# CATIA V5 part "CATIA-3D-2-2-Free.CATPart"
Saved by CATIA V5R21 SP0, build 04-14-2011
Part number: CATIA-3D-2-2-Free
Bounding box of the stored display mesh (mm): x -170 to 0, y -33 to 33, z 0 to 80
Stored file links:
  C:\Users\Rasoul Mohammadi\Desktop\CATIA-Free\3D\CATIA-3D-2-2-Free.CATPart
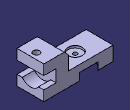
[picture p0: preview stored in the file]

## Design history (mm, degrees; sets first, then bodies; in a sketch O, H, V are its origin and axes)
Body1 (main body)
  Sketch1 on zx-plane, origin (0, 0, 0), H (-1, 0, 0), V (0, 0, 1)
    line L1 (0, 0) -> (0, 25)
    line L2 (0, 25) -> (30, 25)
    line L3 (30, 25) -> (30, 55)
    line L4 (30, 55) -> (0, 55)
    point P4 (0, 55)
    line L5 (0, 55) -> (0, 80)
    line L6 (0, 80) -> (60, 80)
    line L7 (60, 80) -> (60, 35)
    line L8 (60, 35) -> (170, 35)
    line L9 (170, 35) -> (170, 0)
    point P9 (170, 0)
    line L10 (170, 0) -> (0, 0)
    length L4 = 30
    length L1 = 25
    distance L2 L4 = 30
    distance L6 L10 = 80
    distance L1 L9 = 170
    length L9 = 35
    length L6 = 60
    vertical: L1 V, L3 V, L5 V, L7 V, L9 V
    horizontal: L2 H, L4 H, L8 H, L10 H, L6 H
    coincidence: P4 V, P9 H
  Pad1: profile Sketch1, direction (0, 1, 0), length 33, mirrored extent
  Sketch2 on face of Pad1 from Sketch1.L1, origin (0, 0, 0), H (0, 1, 0), V (0, 0, 1)
    arc A1 centre (0, 40) radius 25 from (-20, 25) to (20, 25) ccw
    point P1 (0, 40)
    projected line E1 (-33, 25) -> (33, 25) from edge [face of Pad1 from Sketch1.L1 | face of Pad1 from Sketch1.L2]
    projected line E2 (-20, 25) -> (20, 25) from edge [face of Pad1 from Sketch1.L1 | face of Pad1 from Sketch1.L2]
    point P4 (20, 25)
    point P5 (-20, 25)
    distance H P1 = 40
    radius A1 = 25
    coincidence: P1 V, E1 P4, E1 P5
  Pocket1: profile Sketch2, direction (-1, 0, 0), up to face of Pad1 from Sketch1.L3
  Sketch3 on face of Pad1 from Sketch1.L8, origin (-125.9913, -1.8062, 35), H (1, 0, 0), V (0, 1, 0)
    point P1 (15.9913, 1.8062)
    reference intersected line E1 through (0, 1.8062) direction (-1, 0) from zx-plane
    reference projected line E2 (-44.0087, -31.1938) -> (-44.0087, 34.8062) from edge [face of Pad1 from Sketch1.L8 | face of Pad1 from Sketch1.L9]
    distance P1 E2 = 60
    coincidence: P1 E1
  Hole1: placed by Sketch3, at (-110, 0, 35) direction (0, 0, -1), diameter 10, through (limit type 6), counterbore diameter 35, counterbore depth 5
  Sketch4 on face of Pad1 from Sketch1.L10, origin (0, 0, 0), H (1, 0, 0), V (0, -1, 0)
    circle A1 centre (-110, 0) radius 40
    point P1 (-110, 0)
    reference projected circle E1 centre (-110, 0) radius 5 from edge [face of Hole1 | face of Pad1 from Sketch1.L10]
    radius A1 = 40
    coincidence: P1 H
    concentricity: E1 A1
  Pocket2: profile Sketch4, direction (0, 0, 1), length 18
  Chamfer1: length 10, angle 45, on edge [face of Pad1 from Sketch1.L6 | face of Pad1 from Sketch1.L7]
  Sketch5 on face of Pad1 from Sketch1.L6, origin (-16.0094, 0.1848, 80), H (1, 0, 0), V (0, 1, 0)
    point P1 (1.0094, -0.1848)
    reference projected line E1 (-43.9906, 32.8152) -> (16.0094, 32.8152) from edge [face of Pad1 from Sketch1.L6 | end face of Pad1]
    reference projected line E2 (16.0094, -33.1848) -> (16.0094, 32.8152) from edge [face of Pad1 from Sketch1.L5 | face of Pad1 from Sketch1.L6]
    distance P1 E1 = 33
    distance E2 P1 = 15
  Hole2: placed by Sketch5, at (-15, 0, 80) direction (0, 0, -1), diameter 16, through (limit type 6)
